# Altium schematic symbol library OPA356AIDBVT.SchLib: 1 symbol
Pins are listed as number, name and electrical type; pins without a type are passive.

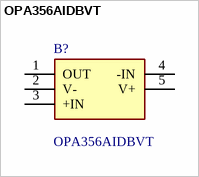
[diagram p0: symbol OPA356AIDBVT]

## OPA356AIDBVT
designator B?
Texas Instruments OPA356AIDBVT Op Amp, 200MHz CMOS, Rail to Rail, 3 V, 5 V, 5-Pin SOT-23; Geometry.Height: 1.45mm
footprint SOT95P280X145-5N
pins: 1 OUT, 2 V-, 3 +IN, 4 -IN, 5 V+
